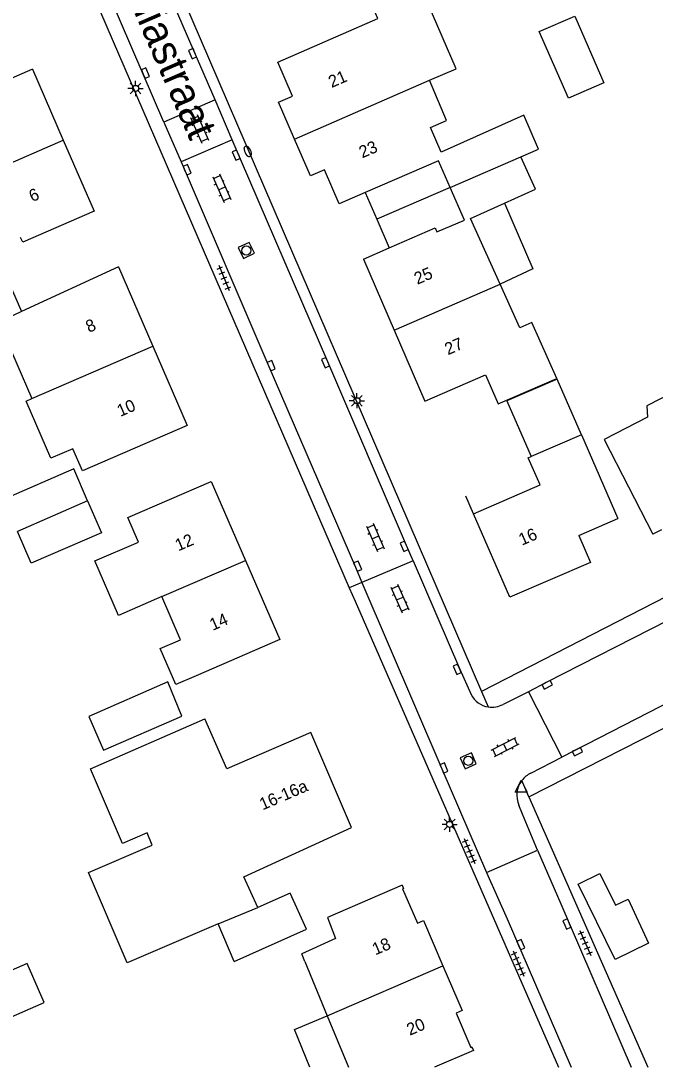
# Model space of a CAD drawing. Extents: x 136000 to 138005, y 398500 to 400500.
# Drawn here: x 137540.9 to 137593.2, y 398500 to 398586.2 of the extents above; entities that cross this region are included whole.
import ezdxf

# ---------------------------------------------------------------- set-up
doc = ezdxf.new("R2010")
doc.units = 0
for name, color, linetype in [('gg-afsc-muur', 7, 'Continuous'), ('gg-anno-huisnummerreeks BGT', 7, 'Continuous'), ('gg-anno-openbare ruimte label', 7, 'Continuous'), ('gg-bbg-bijgebouw', 7, 'Continuous'), ('gg-bbg-gedigitaliseerde bebouwing', 7, 'Continuous'), ('gg-bbg-gedigitaliseerde bijgebouw', 7, 'Continuous'), ('gg-bbg-hoofdgebouw', 7, 'Continuous'), ('gg-bbg-luifel en loopbrug', 7, 'Continuous'), ('gg-bbg-tussenscheiding', 7, 'Continuous'), ('gg-knt-verharding', 7, 'Continuous'), ('gt-grn-weggrens', 7, 'Continuous'), ('gt-symb-brandkraan', 7, 'Continuous'), ('gt-symb-klinker verharding', 7, 'Continuous'), ('gt-symb-kolk', 7, 'Continuous'), ('gt-symb-lichtmast', 7, 'Continuous'), ('gt-symb-rioolschacht', 7, 'Continuous'), ('gt-symb-tegel verharding', 7, 'Continuous'), ('gt-symb-waterafsluiter', 7, 'Continuous')]:
    doc.layers.add(name, color=color, linetype=linetype)

# ---------------------------------------------------------------- blocks, each defined once
blk = doc.blocks.new('gt0-KOLK')
at = {"layer": 'gt-symb-kolk'}
blk.add_lwpolyline([(0, 0), (0.375, 0), (0.375, 0.4), (-0.375, 0.4), (-0.375, 0), (0, 0)], dxfattribs=at)
blk = doc.blocks.new('gt0-KL1')
at = {"layer": 'gt-symb-klinker verharding'}
for p, q in [((-1.15, 0.3), (1.15, 0.3)), ((-1, -0.3), (-1, 0.3)), ((-0.5, 0.3), (-0.5, 0.45)), ((0, -0.3), (0, 0.3)), ((0.5, 0.3), (0.5, 0.45)), ((1, -0.3), (1, 0.3)), ((-1.15, -0.3), (1.15, -0.3)), ((-0.5, -0.45), (-0.5, -0.3)), ((0.5, -0.45), (0.5, -0.3))]:
    blk.add_line(p, q, dxfattribs=at)
blk = doc.blocks.new('gt0-LMAST')
at = {"layer": 'gt-symb-lichtmast'}
for p, q in [((-0.182, 0.173), (-0.447, 0.438)), ((-0.005, 0.246), (-0.005, 0.621)), ((0.172, 0.173), (0.437, 0.438)), ((-0.255, -0.004), (-0.63, -0.004)), ((-0.182, -0.181), (-0.447, -0.446)), ((-0.005, -0.254), (-0.005, -0.629)), ((0.437, -0.446), (0.172, -0.181)), ((0.245, -0.004), (0.62, -0.004))]:
    blk.add_line(p, q, dxfattribs=at)
blk.add_circle((-0.005, -0.004), 0.25, dxfattribs=at)
blk = doc.blocks.new('gt0-TEG1')
at = {"layer": 'gt-symb-tegel verharding'}
for p, q in [((-1.125, 0), (1.125, 0)), ((-0.9, -0.25), (-0.9, 0.25)), ((-0.45, -0.25), (-0.45, 0.25)), ((0, -0.25), (0, 0.25)), ((0.45, -0.25), (0.45, 0.25)), ((0.9, -0.25), (0.9, 0.25))]:
    blk.add_line(p, q, dxfattribs=at)
blk = doc.blocks.new('gt0-RS')
at = {"layer": 'gt-symb-rioolschacht'}
blk.add_lwpolyline([(-0.5, -0.5), (0.5, -0.5), (0.5, 0.5), (-0.5, 0.5)], close=True, dxfattribs=at)
blk.add_circle((0, 0), 0.375, dxfattribs=at)
blk = doc.blocks.new('gt0-BR')
at = {"layer": 'gt-symb-brandkraan'}
for centre, radius, start, end in [((-0.244, 0), 0.206, 107.56694, 252.43307), ((0.599, -2.664), 3, 106.89205, 107.56694), ((0, -0.691), 0.938, 73.10799, 106.89205), ((-0.599, -2.664), 3, 72.43309, 73.10799), ((0.244, 0), 0.206, 287.56695, 72.43309), ((0.599, 2.664), 3, 252.43307, 253.10797), ((0, 0.691), 0.938, 253.10797, 286.89206), ((-0.599, 2.664), 3, 286.89206, 287.56695)]:
    blk.add_arc(centre, radius, start, end, dxfattribs=at)
blk = doc.blocks.new('gt0-WAFSL')
at = {"layer": 'gt-symb-waterafsluiter'}
for p, q in [((-0.5, -0.333), (0, 0.667)), ((0, 0.667), (0.5, -0.333)), ((0.5, -0.333), (-0.5, -0.333))]:
    blk.add_line(p, q, dxfattribs=at)

msp = doc.modelspace()

# ---------------------------------------------------------------- linework, layer by layer
at = {"layer": 'gg-afsc-muur'}
msp.add_line((137578.215, 398545.581), (137577.587, 398547.028), dxfattribs=at)
at = {"layer": 'gg-bbg-bijgebouw'}
for points in [[(137592.612, 398510.206), (137589.871, 398508.862), (137586.821, 398515.072)], [(137558.507, 398508.692), (137564.453, 398511.36), (137563.126, 398514.32), (137560.464, 398513.159)]]:
    msp.add_lwpolyline(points, dxfattribs=at)
at = {"layer": 'gg-bbg-gedigitaliseerde bebouwing'}
for p, q in [((137548.97, 398565.93), (137540.995, 398562.245)), ((137539.375, 398560.779), (137541.845, 398555.079)), ((137554.63, 398552.86), (137547.67, 398549.842)), ((137562.26, 398535.22), (137555.388, 398532.241)), ((137564.334, 398508.684), (137564.067, 398509.333)), ((137564.334, 398508.684), (137566.176, 398504.211)), ((137566.176, 398504.211), (137567.91, 398500))]:
    msp.add_line(p, q, dxfattribs=at)
for points in [[(137574.594, 398581.295), (137576.793, 398582.245), (137574.479, 398587.566)], [(137574.672, 398577.403), (137575.991, 398577.972), (137574.594, 398581.295)], [(137582.119, 398575), (137583.575, 398575.633), (137582.36, 398578.428), (137575.553, 398575.377), (137574.672, 398577.403)], [(137580.757, 398571.168), (137583.321, 398572.318), (137582.119, 398575)], [(137580.405, 398564.493), (137577.974, 398569.92), (137580.757, 398571.168)], [(137546.98, 398570.52), (137541.094, 398567.955), (137540.921, 398568.353)], [(137580.241, 398554.632), (137585.087, 398556.734), (137583.03, 398561.35), (137582.017, 398560.895), (137580.405, 398564.493)], [(137540.995, 398562.245), (137539.116, 398561.377), (137539.375, 398560.779)], [(137595.759, 398556.162), (137592.485, 398554.486), (137592.539, 398553.535)], [(137547.67, 398549.842), (137546.014, 398549.124), (137545.228, 398550.937), (137543.415, 398550.151), (137541.368, 398554.872), (137541.845, 398555.079)], [(137592.539, 398553.535), (137588.97, 398551.706), (137592.97, 398543.901)], [(137550.616, 398543.245), (137549.738, 398545.271), (137556.61, 398548.25)], [(137552.563, 398538.756), (137548.987, 398537.206), (137547.041, 398541.695), (137550.616, 398543.245)], [(137555.388, 398532.241), (137553.697, 398531.508), (137552.409, 398534.477), (137554.101, 398535.21), (137552.563, 398538.756)], [(137557.183, 398511.79), (137549.7, 398508.593), (137546.519, 398516.039), (137551.768, 398518.282), (137551.336, 398519.293), (137549.313, 398518.429), (137546.687, 398524.569), (137556.1, 398528.7)], [(137572.349, 398514.998), (137566.202, 398512.309), (137566.842, 398510.6), (137564.067, 398509.333)]]:
    msp.add_lwpolyline(points, dxfattribs=at)
at = {"layer": 'gg-bbg-gedigitaliseerde bijgebouw'}
msp.add_line((137558.507, 398508.692), (137557.183, 398511.79), dxfattribs=at)
for points in [[(137587.099, 398552.097), (137585.109, 398556.684), (137580.972, 398554.889), (137582.962, 398550.302)], [(137546.436, 398546.661), (137545.302, 398549.277), (137539.509, 398546.766), (137539.751, 398546.207)], [(137546.436, 398546.661), (137547.584, 398544.012), (137541.791, 398541.501), (137540.657, 398544.117)], [(137546.537, 398528.895), (137547.755, 398526.1), (137554.202, 398528.909), (137553.042, 398531.729), (137546.537, 398528.895)], [(137586.821, 398515.072), (137588.616, 398515.954), (137589.904, 398513.332), (137590.946, 398513.844), (137592.612, 398510.206)], [(137536.958, 398502.751), (137542.868, 398505.333), (137541.465, 398508.542), (137535.48, 398505.927)]]:
    msp.add_lwpolyline(points, dxfattribs=at)
at = {"layer": 'gg-bbg-hoofdgebouw'}
for p, q in [((137563.309, 398579.99), (137562.09, 398582.8)), ((137541.897, 398582.197), (137544.44, 398576.355)), ((137544.44, 398576.355), (137546.98, 398570.52)), ((137567.16, 398571.11), (137565.937, 398573.929)), ((137569.296, 398572.039), (137567.16, 398571.11)), ((137569.16, 398566.56), (137571.277, 398567.48)), ((137569.16, 398566.56), (137571.69, 398560.716)), ((137548.97, 398565.93), (137551.8, 398559.395)), ((137551.8, 398559.395), (137554.63, 398552.86)), ((137587.099, 398552.097), (137590.098, 398545.188)), ((137556.61, 398548.25), (137559.435, 398541.735)), ((137586.879, 398543.788), (137590.098, 398545.188)), ((137593.682, 398544.265), (137592.97, 398543.901)), ((137559.435, 398541.735), (137562.26, 398535.22))]:
    msp.add_line(p, q, dxfattribs=at)
for points in [[(137562.09, 398582.8), (137570.329, 398586.373), (137569.336, 398588.661)], [(137541.897, 398582.197), (137535.93, 398579.613), (137536.058, 398579.315), (137533.753, 398578.321), (137532.742, 398580.859)], [(137563.478, 398576.455), (137562.155, 398579.49), (137563.309, 398579.99)], [(137565.937, 398573.929), (137564.795, 398573.432), (137563.478, 398576.455)], [(137576.296, 398572.471), (137575.341, 398574.667), (137569.296, 398572.039)], [(137571.277, 398567.48), (137575.062, 398569.126), (137575.204, 398568.799), (137577.465, 398569.782), (137576.296, 398572.471)], [(137571.69, 398560.716), (137574.22, 398554.871), (137579.203, 398557.028), (137580.241, 398554.632)], [(137578.215, 398545.581), (137583.7, 398547.96), (137582.727, 398550.2), (137582.962, 398550.302)], [(137586.879, 398543.788), (137587.84, 398541.58), (137581.2, 398538.7), (137578.215, 398545.581)], [(137568.18, 398519.74), (137564.81, 398527.55), (137557.91, 398524.57), (137556.1, 398528.7)], [(137560.464, 398513.159), (137559.313, 398515.659), (137568.18, 398519.74)], [(137572.349, 398514.998), (137572.463, 398514.724), (137572.367, 398514.683), (137573.59, 398511.86), (137574.096, 398512.077), (137575.691, 398508.353)], [(137575.691, 398508.353), (137577.271, 398504.665), (137576.777, 398504.446), (137577.99, 398501.622), (137578.088, 398501.664), (137578.217, 398501.378), (137575.001, 398500)]]:
    msp.add_lwpolyline(points, dxfattribs=at)
at = {"layer": 'gg-bbg-luifel en loopbrug'}
for p, q in [((137576.296, 398572.471), (137570.25, 398569.843)), ((137569.296, 398572.039), (137570.25, 398569.843)), ((137570.25, 398569.843), (137571.277, 398567.48)), ((137539.975, 398564.594), (137540.995, 398562.245))]:
    msp.add_line(p, q, dxfattribs=at)
for points in [[(137583.633, 398585.304), (137586.55, 398586.575), (137588.943, 398581.082), (137586.026, 398579.811), (137583.633, 398585.304)], [(137580.757, 398571.168), (137583.111, 398565.773), (137580.405, 398564.493)], [(137564.748, 398500), (137563.469, 398503.091), (137566.176, 398504.211)]]:
    msp.add_lwpolyline(points, dxfattribs=at)
at = {"layer": 'gg-bbg-tussenscheiding'}
for p, q in [((137563.478, 398576.455), (137574.594, 398581.295)), ((137538.554, 398573.79), (137544.44, 398576.355)), ((137576.296, 398572.471), (137582.119, 398575)), ((137571.69, 398560.716), (137580.405, 398564.493)), ((137541.845, 398555.079), (137551.8, 398559.395)), ((137587.099, 398552.097), (137582.962, 398550.302)), ((137546.436, 398546.661), (137540.657, 398544.117)), ((137552.563, 398538.756), (137559.435, 398541.735)), ((137557.183, 398511.79), (137560.464, 398513.159)), ((137566.176, 398504.211), (137575.691, 398508.353))]:
    msp.add_line(p, q, dxfattribs=at)
at = {"layer": 'gg-knt-verharding'}
for p, q in [((137543.51, 398613.045), (137578.87, 398530.95)), ((137539.7, 398605.01), (137567.989, 398539.482)), ((137556.938, 398579.679), (137552.716, 398577.842)), ((137558.352, 398576.394), (137556.938, 398579.679)), ((137552.716, 398577.842), (137554.139, 398574.568)), ((137558.352, 398576.394), (137554.139, 398574.568)), ((137582.78, 398522.25), (137673.433, 398568.681)), ((137573.244, 398541.705), (137569.021, 398539.912)), ((137582.746, 398530.919), (137580.645, 398529.878)), ((137582.746, 398530.919), (137585.477, 398525.543)), ((137582.943, 398524.221), (137585.477, 398525.543)), ((137582.78, 398522.25), (137592.563, 398500)), ((137579.274, 398516.027), (137583.473, 398517.876)), ((137583.473, 398517.876), (137585.408, 398513.44)), ((137579.274, 398516.027), (137580.976, 398512.224)), ((137585.408, 398513.44), (137591.206, 398500)), ((137580.976, 398512.224), (137586.258, 398500))]:
    msp.add_line(p, q, dxfattribs=at)
for points in [[(137556.938, 398579.679), (137551.598, 398592.048), (137546.651, 398603.59), (137545.793, 398605.623)], [(137552.716, 398577.842), (137547.444, 398590.125), (137542.944, 398600.405), (137541.479, 398603.839)], [(137686.898, 398586.151), (137681.9, 398583.55), (137661.88, 398573.42), (137660.16, 398572.71), (137578.87, 398530.95)], [(137573.244, 398541.705), (137572.687, 398542.973), (137566.211, 398558.11), (137558.352, 398576.394)], [(137554.139, 398574.568), (137561.375, 398557.705), (137568.49, 398541.186), (137569.021, 398539.912)], [(137629.912, 398555.032), (137611.282, 398545.499), (137584.191, 398531.67), (137582.746, 398530.919)], [(137632.67, 398549.661), (137631.165, 398548.863), (137598.676, 398532.317), (137585.477, 398525.543)], [(137573.244, 398541.705), (137577.049, 398532.838), (137578.013, 398530.691)], [(137569.021, 398539.912), (137575.595, 398524.567), (137579.274, 398516.027)], [(137567.989, 398539.482), (137568.465, 398538.378), (137585.22, 398500)], [(137583.473, 398517.876), (137582.241, 398520.828), (137581.945, 398521.581)]]:
    msp.add_lwpolyline(points, dxfattribs=at)
for centre, radius, start, end in [((137579.725, 398531.567), 1.923, 207.10456, 260.93262), ((137579.725, 398531.567), 1.923, 260.91987, 298.5665), ((137583.816, 398522.383), 2.034, 115.40294, 143.23356), ((137583.817, 398522.382), 2.036, 143.2258, 203.16695)]:
    msp.add_arc(centre, radius, start, end, dxfattribs=at)
at = {"layer": 'gt-grn-weggrens'}
for p, q in [((137569.021, 398539.912), (137567.989, 398539.482)), ((137578.87, 398530.95), (137579.422, 398529.668)), ((137582.78, 398522.25), (137582.186, 398523.601))]:
    msp.add_line(p, q, dxfattribs=at)

# ---------------------------------------------------------------- block references
at = {"layer": 'gt-symb-brandkraan', "rotation": 115.87933915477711}
msp.add_blockref('gt0-BR', (137559.626, 398575.441), dxfattribs=at)
at = {"layer": 'gt-symb-klinker verharding'}
for p, rotation in [((137555.66, 398577.296), -66.22952419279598), ((137557.483, 398572.403), -66.22952419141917), ((137570.131, 398543.637), -66.22952419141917), ((137572.146, 398538.6), -66.22952419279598), ((137580.82, 398526.365), 26.872538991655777)]:
    msp.add_blockref('gt0-KL1', p, dxfattribs=dict(at, rotation=rotation))
at = {"layer": 'gt-symb-kolk'}
for p, rotation in [((137555.269, 398583.565), 113.24309290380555), ((137551.019, 398581.804), -66.75690709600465), ((137558.854, 398575.203), 113.28972450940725), ((137554.45, 398573.841), -66.84379428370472), ((137561.375, 398557.705), -66.77492045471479), ((137566.211, 398558.11), 113.16362499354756), ((137572.687, 398542.973), 113.70931388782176), ((137568.49, 398541.186), -66.69545151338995), ((137577.049, 398532.838), 114.18616825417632), ((137584.191, 398531.67), -152.9766212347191), ((137586.682, 398526.155), -153.07403530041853), ((137575.595, 398524.567), -66.80776744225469), ((137585.725, 398511.703), -66.61335784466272), ((137581.925, 398510.008), -66.61335784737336)]:
    msp.add_blockref('gt0-KOLK', p, dxfattribs=dict(at, rotation=rotation))
at = {"layer": 'gt-symb-lichtmast'}
for p in [(137550.395, 398580.627), (137568.617, 398554.9), (137576.256, 398519.997)]:
    msp.add_blockref('gt0-LMAST', p, dxfattribs=at)
at = {"layer": 'gt-symb-rioolschacht'}
for p, rotation in [((137559.516, 398567.273), 115.76381431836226), ((137577.783, 398525.233), -156.04160802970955)]:
    msp.add_blockref('gt0-RS', p, dxfattribs=dict(at, rotation=rotation))
at = {"layer": 'gt-symb-tegel verharding'}
for p, rotation in [((137557.668, 398565.009), -67.71962896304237), ((137577.89, 398517.807), -66.8690905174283), ((137587.418, 398510.222), -66.79388541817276), ((137581.92, 398508.53), -66.79388541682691)]:
    msp.add_blockref('gt0-TEG1', p, dxfattribs=dict(at, rotation=rotation))
at = {"layer": 'gt-symb-waterafsluiter'}
msp.add_blockref('gt0-WAFSL', (137582.131, 398522.981), dxfattribs=at)

# ---------------------------------------------------------------- texts
at = {"layer": 'gg-anno-huisnummerreeks BGT'}
for s, rotation, p in [('21', 23.4, (137566.533, 398580.656)), ('23', 23.4, (137569.048, 398574.856)), ('6', 23.5, (137541.877, 398571.248)), ('25', 23.4, (137573.588, 398564.442)), ('8', 23.4, (137546.546, 398560.481)), ('27', 23.4, (137576.102, 398558.635)), ('10', 23.4, (137549.124, 398553.552)), ('12', 23.5, (137553.905, 398542.478)), ('16', 23.5, (137582.197, 398542.947)), ('14', 23.5, (137556.743, 398535.933)), ('16-16a', 23.3, (137560.849, 398521.144)), ('18', 23.2, (137570.132, 398509.2)), ('20', 23.2, (137572.97, 398502.575))]:
    msp.add_text(s, height=1, rotation=rotation, dxfattribs=at).set_placement(p)
at = {"layer": 'gg-anno-openbare ruimte label'}
msp.add_text('Sint Caeciliastraat', height=2.5, rotation=293.5, dxfattribs=at).set_placement((137544.145, 398600.95))

doc.saveas('drawing.dxf')
